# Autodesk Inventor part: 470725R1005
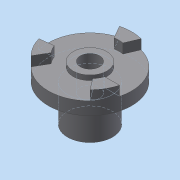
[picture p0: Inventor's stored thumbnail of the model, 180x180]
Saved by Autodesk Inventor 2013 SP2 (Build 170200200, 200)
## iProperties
Created: 2017-07
Part Number: 470725R1005
Material: 일반
Document SubType Name: Modeling
Designer: sd
Density: 1 g/cm^3
Author: sd
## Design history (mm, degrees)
sketch "스케치1"
  geometry: C1 r 52 at (0, 0); C2 r 28 at (0, 0); 1 further point
  constraints: 2 centre point, 2 coincident
  dimensions: "d0" = 104 diameter of C1; "d1" = 56 diameter of C2
extrude "돌출1" new body sketch "스케치1" distance "d2" = 16; taper "d3" = 0 deg
extrude "돌출2" join sketch "스케치1" distance "d4" = 16; taper "d6" = 0 deg; dims "d5" = 46, "d7" = 0
sketch "스케치2"
  geometry: C1 r 52 at (0, 0) reference; C2 r 21 at (0, 0); C3 r 12 at (0, 0)
  constraints: 2 centre point, 2 coincident
  dimensions: "d10" = 42 diameter of C2; "d11" = 24 diameter of C3
extrude "돌출3" join sketch "스케치2" distance "d12" = 6; taper "d13" = 0 deg
extrude "돌출4" cut sketch "스케치2" distance "d14" = 28; taper "d15" = 0 deg
sketch "스케치3"
  geometry: L1 (0, 0)-(-13.851, 51.654); L2 (0, 0)-(13.449, 50.231); L3 (0, 0)-(45.038, -25.992); L4 (0, 0)-(-45.029, -26.008); L5 (-50.226, -13.468)-(-33.159, -11.379); L6 (-33.159, -11.379)-(-27.63, -20.951); L7 (-27.63, -20.951)-(-36.763, -36.776); L8 (36.776, -36.763)-(26.434, -23.027); L9 (26.434, -23.027)-(31.959, -13.453); L10 (31.959, -13.453)-(50.231, -13.449); L11 (13.449, 50.231)-(6.725, 34.406); L12 (6.725, 34.406)-(-4.329, 34.404); L13 (-4.329, 34.404)-(-13.468, 50.226); L14 (0, 0)-(-0.003, 17.748); L15 (-13.468, 50.226)-(-18.391, 56.765); L16 (13.449, 50.231)-(14.574, 52.876); C1 r 21 at (0, 0) reference; A1 r 32 centre (-3.101, -0.401) between (-33.159, -11.379) and (-27.63, -20.951); A2 r 32 centre (1.897, -2.485) between (26.434, -23.027) and (31.959, -13.453); A3 r 32 centre (1.204, 2.886) between (6.725, 34.406) and (-4.329, 34.404); 3 further points
  constraints: 32 end point, 6 point on circle, 3 centre point, 3 perpendicular, 1 coincident, 1 collinear, 1 parallel, 1 point on line, 39 other
  dimensions: "d16" = 120 deg angle of L3 L4; "d17" = 30 deg angle of L2 L1; "d19" = 32 radius of A1; "d22" = 360 deg dimension on point (0, 0) L4.end (derived); "d24" = 15 deg angle of L1 L14
extrude "돌출5" join sketch "스케치3" distance "d26" = 12; taper "d27" = 0 deg
node "솔리드1"
pattern_circular "원형 패턴1" dims angle "d29" = 360 deg
